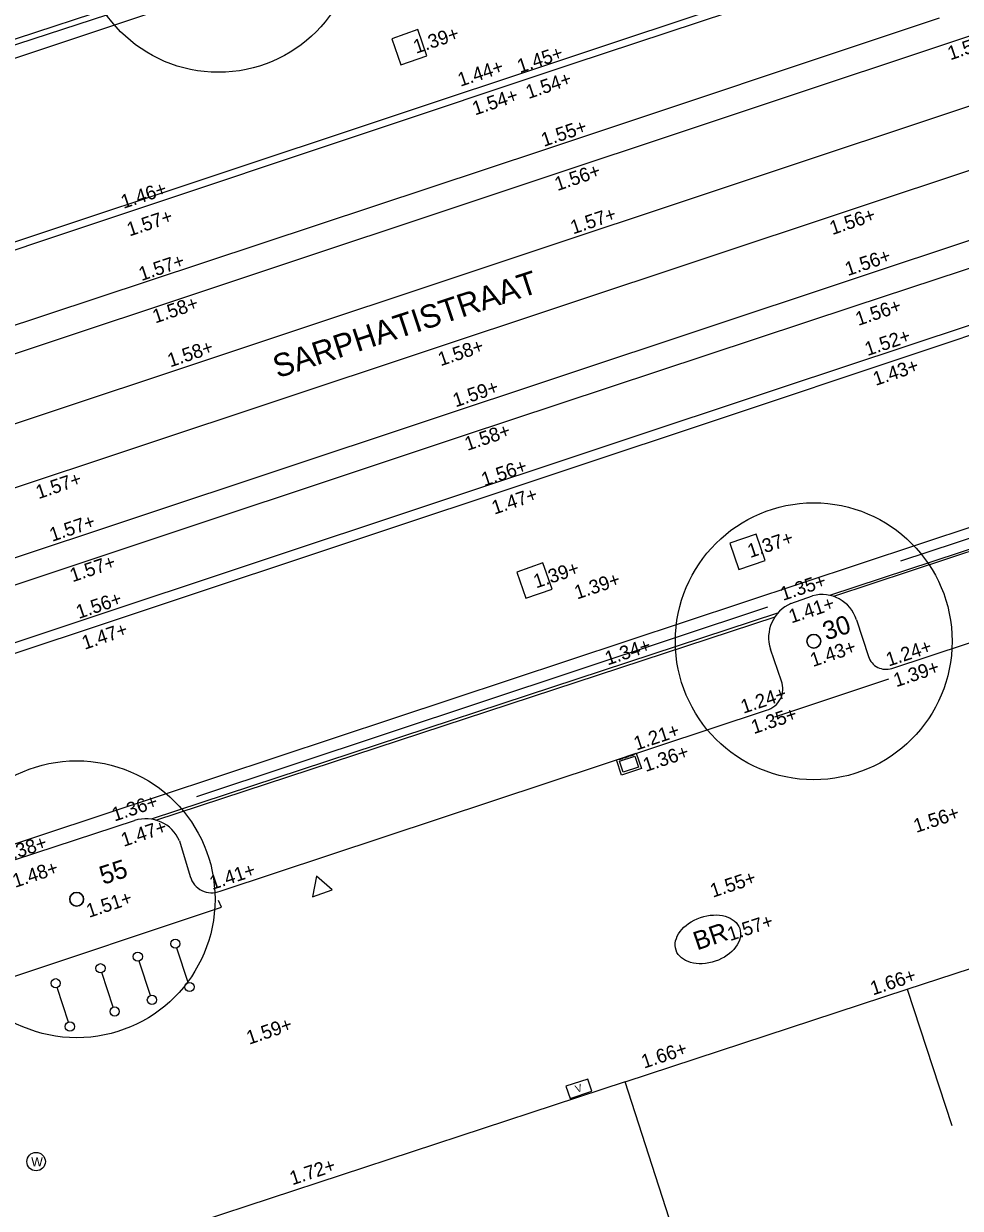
# Model space of a CAD drawing. Extents: x 122462 to 123306, y 485548 to 486417.
# Drawn here: x 122686.41 to 122706.71, y 486120.56 to 486146.23 of the extents above; entities that cross this region are included whole.
import ezdxf

# ---------------------------------------------------------------- set-up
doc = ezdxf.new("R2010")
doc.units = 0
for name, color, linetype in [('B meubilair trammast', 7, 'Continuous'), ('B RWS-band 115-225x250 mm specie', 7, 'Continuous'), ('B-WE-GR-BOOM_BOOMDIAMETER', 7, 'Continuous'), ('B-WE-IE-MEUBILAIR_WEGMEUBILAIR_FIETSNIETJE-S', 7, 'Continuous'), ('B-WE-KL-DATA_TELECOM_KAST-S', 7, 'Continuous'), ('B-WE-OG-HOOGTEPUNT-S', 7, 'Continuous'), ('B-WE-OG-TOPOGRAFIE_RAILS-G', 7, 'Continuous'), ('B-WE-OG-TOPOGRAFIE_STRAATNAAM', 7, 'Continuous'), ('B-WE-OG-TOPOKAART-G', 7, 'Continuous'), ('B-WE-RI-HWA_KOLK-S', 7, 'Continuous'), ('B-WE-RI-HWA_RIOOLPUT-S', 7, 'Continuous'), ('B-WE-VH-KANTOPSLUITING_OPSLUITBAND_100X200-G', 7, 'Continuous'), ('B-WE-VH-KANTVERHARDING_EIND_VERHARDING-G', 7, 'Continuous'), ('B-WE-VH-MATERIAALGRENS-G', 7, 'Continuous'), ('B-WE-VH-MATERIAALGRENS_ASFALT-G', 7, 'Continuous'), ('B-WE-VW-MARKERING_LANGS_STREEP_11_010-G', 7, 'Continuous'), ('B-WE-VW-MARKERING_LANGS_STREEP_DOORGETROKKEN_010-G', 7, 'Continuous'), ('iba7-verkeersbord blauw', 7, 'Continuous'), ('iba7-verkeersbord rood', 7, 'Continuous'), ('V-WE-GR-BOOM-S', 7, 'Continuous')]:
    doc.layers.add(name, color=color, linetype=linetype)

msp = doc.modelspace()

# ---------------------------------------------------------------- linework, layer by layer
at = {"layer": 'B meubilair trammast'}
msp.add_lwpolyline([(122692.665, 486127.315), (122693.091, 486127.46), (122692.752, 486127.756)], close=True, dxfattribs=at)
at = {"layer": 'B RWS-band 115-225x250 mm specie'}
for points in [[(122669.847, 486135.87), (122698.323, 486145.37), (122705.772, 486147.833)], [(122708.301, 486140.155), (122702.829, 486138.34), (122672.345, 486128.207)]]:
    msp.add_lwpolyline(points, dxfattribs=at)
at = {"layer": 'B-WE-IE-MEUBILAIR_WEGMEUBILAIR_FIETSNIETJE-S'}
for p, q in [((122689.971, 486125.454), (122689.727, 486126.202)), ((122689.156, 486125.174), (122688.911, 486125.921)), ((122688.348, 486124.922), (122688.103, 486125.669)), ((122687.376, 486124.596), (122687.132, 486125.344))]:
    msp.add_line(p, q, dxfattribs=at)
for centre in [(122689.695, 486126.297), (122688.88, 486126.016), (122688.072, 486125.764), (122687.1, 486125.439), (122690.003, 486125.359), (122689.187, 486125.079), (122688.379, 486124.827), (122687.408, 486124.501)]:
    msp.add_circle(centre, 0.1, dxfattribs=at)
at = {"layer": 'B-WE-KL-DATA_TELECOM_KAST-S'}
msp.add_lwpolyline([(122698.639, 486123.364), (122698.164, 486123.208), (122698.251, 486122.942), (122698.727, 486123.098)], close=True, dxfattribs=at)
at = {"layer": 'B-WE-OG-TOPOGRAFIE_RAILS-G'}
for p, q in [((122670.505, 486133.859), (122714.919, 486148.627)), ((122670.96, 486132.492), (122715.373, 486147.26)), ((122671.366, 486131.239), (122712.39, 486144.878)), ((122671.82, 486129.872), (122712.845, 486143.511))]:
    msp.add_line(p, q, dxfattribs=at)
at = {"layer": 'B-WE-OG-TOPOKAART-G'}
msp.add_lwpolyline([(122700.399, 486120.349), (122699.445, 486123.3), (122688.673, 486119.763), (122689.048, 486118.623), (122683.871, 486116.922), (122683.497, 486118.062), (122676.455, 486115.749)], dxfattribs=at)
at = {"layer": 'B-WE-RI-HWA_KOLK-S'}
for p, q in [((122699.261, 486130.282), (122699.688, 486130.424)), ((122699.367, 486130.302), (122699.398, 486130.312)), ((122699.403, 486130.329), (122699.404, 486130.325)), ((122699.427, 486130.337), (122699.428, 486130.332)), ((122699.441, 486130.326), (122699.517, 486130.351)), ((122699.522, 486130.369), (122699.523, 486130.364)), ((122699.545, 486130.376), (122699.547, 486130.372)), ((122699.56, 486130.365), (122699.635, 486130.391)), ((122699.64, 486130.408), (122699.642, 486130.403)), ((122699.688, 486130.424), (122699.798, 486130.091)), ((122699.371, 486129.95), (122699.261, 486130.282)), ((122699.308, 486130.298), (122699.31, 486130.293)), ((122699.322, 486130.287), (122699.367, 486130.302)), ((122699.798, 486130.091), (122699.371, 486129.95))]:
    msp.add_line(p, q, dxfattribs=at)
msp.add_lwpolyline([(122699.735, 486130.123), (122699.402, 486130.013), (122699.324, 486130.25), (122699.656, 486130.36)], close=True, dxfattribs=at)
for centre, start, end in [((122699.395, 486130.321), 288.3203, 18.3203), ((122699.438, 486130.336), 198.3203, 288.3203), ((122699.514, 486130.361), 288.3203, 18.3203), ((122699.556, 486130.375), 198.3203, 288.3203), ((122699.632, 486130.4), 288.3203, 18.3203), ((122699.319, 486130.296), 198.3203, 288.3203)]:
    msp.add_arc(centre, 0.01, start, end, dxfattribs=at)
at = {"layer": 'B-WE-RI-HWA_RIOOLPUT-S'}
for points in [[(122694.385, 486145.905), (122694.582, 486145.338), (122695.149, 486145.535), (122694.952, 486146.102)], [(122702.481, 486134.602), (122702.286, 486135.169), (122701.719, 486134.974), (122701.914, 486134.407)], [(122697.861, 486133.98), (122697.663, 486134.546), (122697.097, 486134.348), (122697.295, 486133.782)]]:
    msp.add_lwpolyline(points, close=True, dxfattribs=at)
at = {"layer": 'B-WE-VH-KANTOPSLUITING_OPSLUITBAND_100X200-G'}
msp.add_lwpolyline([(122699.445, 486123.3), (122705.563, 486125.308), (122706.53, 486122.359)], dxfattribs=at)
at = {"layer": 'B-WE-VH-KANTVERHARDING_EIND_VERHARDING-G'}
for points in [[(122702.69, 486131.215), (122705.163, 486132.032)], [(122685.809, 486125.603), (122685.84, 486125.468), (122690.695, 486127.088), (122690.628, 486127.234)]]:
    msp.add_lwpolyline(points, dxfattribs=at)
at = {"layer": 'B-WE-VH-MATERIAALGRENS-G'}
msp.add_lwpolyline([(122705.563, 486125.308), (122708.306, 486126.208)], dxfattribs=at)
at = {"layer": 'B-WE-VH-MATERIAALGRENS_ASFALT-G'}
for points in [[(122689.178, 486146.73), (122682.431, 486144.534), (122673.133, 486141.431), (122670.707, 486140.578), (122670.551, 486140.725)], [(122670.318, 486134.438), (122689.137, 486140.666), (122697.659, 486143.491), (122706.259, 486146.355)], [(122707.935, 486141.266), (122704.407, 486140.099), (122695.913, 486137.294), (122687.388, 486134.451), (122671.994, 486129.333)], [(122709.518, 486135.698), (122703.88, 486133.844)], [(122702.75, 486133.455), (122689.171, 486128.996)]]:
    msp.add_lwpolyline(points, dxfattribs=at)
at = {"layer": 'B-WE-VW-MARKERING_LANGS_STREEP_11_010-G'}
for points in [[(122701.228, 486150.481), (122671.658, 486140.638)], [(122709.603, 486136.203), (122680.508, 486126.571), (122673.652, 486124.285)], [(122709.675, 486135.987), (122705.415, 486134.581)], [(122702.535, 486133.589), (122690.152, 486129.481)]]:
    msp.add_lwpolyline(points, dxfattribs=at)
at = {"layer": 'B-WE-VW-MARKERING_LANGS_STREEP_DOORGETROKKEN_010-G'}
for p, q in [((122718.77, 486138.702), (122703.962, 486133.822)), ((122702.689, 486133.372), (122689.266, 486128.964))]:
    msp.add_line(p, q, dxfattribs=at)
for points in [[(122669.745, 486136.183), (122671.391, 486136.575), (122705.718, 486147.995)], [(122708.366, 486139.96), (122701.962, 486137.822), (122672.4, 486127.989)]]:
    msp.add_lwpolyline(points, dxfattribs=at)
at = {"layer": 'iba7-verkeersbord blauw'}
msp.add_circle((122686.676, 486121.575), 0.2, dxfattribs=at)
msp.add_ellipse((122701.24, 486126.39), major_axis=(-0.69, -0.235), ratio=0.685994, dxfattribs=at)
at = {"layer": 'iba7-verkeersbord rood'}
for centre, radius in [((122690.629, 486148.177), 3), ((122703.536, 486132.849), 3), ((122703.536, 486132.849), 0.15), ((122687.555, 486127.259), 3), ((122687.555, 486127.259), 0.15)]:
    msp.add_circle(centre, radius, dxfattribs=at)
for centre, start, end in [((122703.536, 486132.849), 0, 180), ((122703.536, 486132.849), 180, 0), ((122687.555, 486127.259), 0, 180), ((122687.555, 486127.259), 180, 0)]:
    msp.add_arc(centre, 0.15, start, end, dxfattribs=at)
at = {"layer": 'V-WE-GR-BOOM-S'}
for points in [[(122689.134, 486146.852), (122675.531, 486142.397), (122670.617, 486140.763)], [(122705.227, 486132.261), (122709.32, 486133.608), (122719.352, 486136.936)], [(122703.042, 486133.666), (122703.51, 486133.833)], [(122704.46, 486133.316), (122704.721, 486132.517)], [(122702.834, 486131.988), (122702.598, 486132.678)], [(122690.664, 486127.435), (122702.512, 486131.358)], [(122686.229, 486128.118), (122688.811, 486128.965)], [(122689.786, 486128.522), (122690.018, 486127.754)]]:
    msp.add_lwpolyline(points, dxfattribs=at)
for centre, radius, start, end in [((122703.355, 486132.932), 0.798, 113.0819, 198.5205), ((122703.718, 486133.084), 0.777, 17.3585, 105.5305), ((122705.102, 486132.641), 0.4, 198.1189, 288.2093), ((122702.391, 486131.817), 0.475, 284.7543, 21.1015), ((122689.057, 486128.213), 0.791, 22.9882, 108.1416), ((122690.482, 486127.88), 0.481, 195.2356, 292.2034)]:
    msp.add_arc(centre, radius, start, end, dxfattribs=at)

# ---------------------------------------------------------------- texts
at = {"layer": 'B-WE-GR-BOOM_BOOMDIAMETER'}
for s, rotation, p in [('30', 18.2008, (122703.808, 486132.863)), ('55', 18.3203, (122688.129, 486127.569))]:
    msp.add_text(s, height=0.4, rotation=rotation, dxfattribs=at).set_placement(p)
at = {"layer": 'B-WE-KL-DATA_TELECOM_KAST-S'}
msp.add_text('V', height=0.16, rotation=18.1777, dxfattribs=at).set_placement((122698.396, 486123.066))
at = {"layer": 'B-WE-OG-HOOGTEPUNT-S'}
for s, rotation, p in [('1.39+', 18.4111, (122694.913, 486145.577)), ('1.54+', 18.5941, (122706.497, 486145.435)), ('1.45+', 18.4111, (122697.165, 486145.157)), ('1.44+', 18.4111, (122695.875, 486144.861)), ('1.54+', 18.5941, (122697.352, 486144.595)), ('1.54+', 18.4111, (122696.192, 486144.24)), ('1.55+', 18.5941, (122697.684, 486143.559)), ('1.56+', 18.5941, (122697.978, 486142.602)), ('1.46+', 18.3037, (122688.572, 486142.217)), ('1.57+', 18.3037, (122688.702, 486141.619)), ('1.57+', 18.5941, (122698.32, 486141.663)), ('1.56+', 18.5941, (122703.94, 486141.649)), ('1.57+', 18.5941, (122688.96, 486140.652)), ('1.56+', 18.5941, (122704.272, 486140.759)), ('1.58+', 18.5941, (122689.259, 486139.733)), ('1.56+', 18.5941, (122704.5, 486139.679)), ('1.52+', 18.5941, (122704.701, 486139.026)), ('1.58+', 18.5941, (122689.584, 486138.782)), ('1.58+', 18.5941, (122695.448, 486138.806)), ('1.43+', 18.5941, (122704.879, 486138.38)), ('1.59+', 18.5941, (122695.77, 486137.916)), ('1.58+', 18.5941, (122696.026, 486136.972)), ('1.56+', 18.5941, (122696.388, 486136.202)), ('1.57+', 18.5941, (122686.728, 486135.926)), ('1.47+', 18.3983, (122696.612, 486135.591)), ('1.57+', 18.5941, (122687.025, 486135.003)), ('1.37+', 18.3203, (122702.158, 486134.651)), ('1.57+', 18.5941, (122687.466, 486134.125)), ('1.39+', 18.3203, (122697.517, 486133.993)), ('1.39+', 18.3203, (122698.404, 486133.753)), ('1.35+', 18.3203, (122702.868, 486133.722)), ('1.56+', 18.5941, (122687.601, 486133.331)), ('1.41+', 18.3203, (122703.052, 486133.234)), ('1.47+', 18.5941, (122687.727, 486132.663)), ('1.34+', 18.3203, (122699.067, 486132.325)), ('1.43+', 18.3203, (122703.517, 486132.29)), ('1.24+', 18.3203, (122705.16, 486132.299)), ('1.39+', 18.3203, (122705.323, 486131.852)), ('1.24+', 18.3203, (122702.011, 486131.278)), ('1.35+', 18.3203, (122702.237, 486130.836)), ('1.21+', 18.3203, (122699.691, 486130.481)), ('1.36+', 18.3203, (122699.893, 486130.015)), ('1.36+', 18.1815, (122688.377, 486128.942)), ('1.56+', 18.2074, (122705.757, 486128.695)), ('1.47+', 18.1815, (122688.574, 486128.393)), ('1.38+', 18.1815, (122685.975, 486128.053)), ('1.48+', 18.1815, (122686.22, 486127.505)), ('1.41+', 18.1815, (122690.495, 486127.46)), ('1.55+', 18.2074, (122701.347, 486127.291)), ('1.51+', 18.1815, (122687.822, 486126.854)), ('1.57+', 18.2074, (122701.721, 486126.349)), ('1.66+', 18.2074, (122704.819, 486125.175)), ('1.59+', 18.6944, (122691.295, 486124.105)), ('1.66+', 18.2074, (122699.855, 486123.588)), ('1.72+', 18.1815, (122692.231, 486121.061))]:
    msp.add_text(s, height=0.3, rotation=rotation, dxfattribs=at).set_placement(p)
at = {"layer": 'B-WE-OG-TOPOGRAFIE_STRAATNAAM'}
msp.add_text('SARPHATISTRAAT', height=0.5, rotation=18.2298, dxfattribs=at).set_placement((122691.911, 486138.544))
at = {"layer": 'iba7-verkeersbord blauw'}
msp.add_text('BR', height=0.4, rotation=18.8313, dxfattribs=at).set_placement((122701.007, 486126.149))
msp.add_text('W', height=0.2, dxfattribs=at).set_placement((122686.57, 486121.47))

doc.saveas('drawing.dxf')
